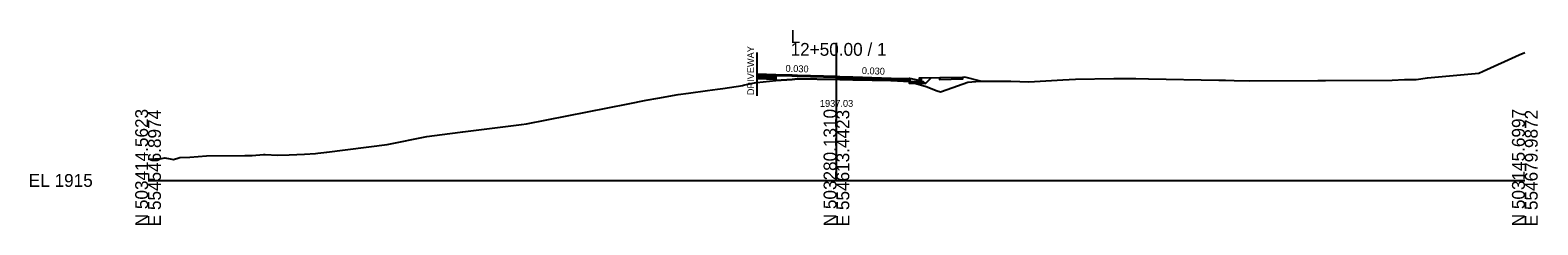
# Model space of a CAD drawing. Extents: x -26 to 4603, y -10 to 4703.
# Drawn here: x -25.7 to 302.8, y 1060.3 to 1102.8 of the extents above; entities that cross this region are included whole.
import ezdxf

# ---------------------------------------------------------------- set-up
doc = ezdxf.new("R2010")
doc.units = 0
for name, color, linetype in [('Default', 7, 'Continuous'), ('Exist Cross Section Cell', 7, 'Continuous'), ('Exist XS Ground Line', 7, 'Continuous'), ('Prop CMT Pvmt Course 1', 7, 'Continuous'), ('Prop CMT Pvmt Course 2', 7, 'Continuous'), ('Prop CMT Pvmt Course 3', 7, 'Continuous'), ('Prop CMT Pvmt Milling', 7, 'Continuous'), ('Prop CMT Shear Line', 7, 'Continuous'), ('Prop CMT Shld Paved Course 2', 7, 'Continuous'), ('Prop CMT Subgrade Earthwork', 7, 'Continuous'), ('Prop Conc 4in Sidewalk', 7, 'Continuous'), ('Prop Conc Curb and Gutter', 7, 'Continuous'), ('Prop Corridor Mesh Bottom', 7, 'Continuous'), ('Prop XS Finish Grade', 7, 'Continuous'), ('Prop XS Label Text', 7, 'Continuous'), ('Prop XS Shear Point Element', 7, 'Continuous'), ('Prop XS Shear Point Label', 7, 'Continuous'), ('Prop XS SS Elevation Text', 7, 'Continuous')]:
    doc.layers.add(name, color=color, linetype=linetype)

msp = doc.modelspace()

# ---------------------------------------------------------------- linework, layer by layer
at = {"layer": 'Exist Cross Section Cell'}
for p, q in [((150, 1070), (150, 1100)), ((0, 1070), (150, 1070)), ((150, 1070), (300, 1070))]:
    msp.add_line(p, q, dxfattribs=at)
at = {"layer": 'Exist XS Ground Line'}
msp.add_lwpolyline([(0, 1074.67), (2.92, 1074.82), (3.65, 1074.97), (4.8, 1074.71), (5.52, 1074.59), (6.72, 1074.96), (6.94, 1075.02), (9.11, 1075.1), (12.76, 1075.38), (21.08, 1075.41), (21.67, 1075.44), (22.66, 1075.48), (25.13, 1075.65), (25.52, 1075.66), (28.17, 1075.51), (30.73, 1075.57), (34.08, 1075.7), (36.49, 1075.89), (36.99, 1075.92), (38.94, 1076.19), (52.08, 1077.83), (60.71, 1079.57), (65.78, 1080.25), (68.59, 1080.64), (80.8, 1082.11), (81.34, 1082.2), (82.46, 1082.38), (104.64, 1086.71), (108.52, 1087.54), (111.05, 1087.94), (115.49, 1088.78), (117.73, 1089.06), (121.9, 1089.6), (124.11, 1089.89), (125.21, 1090.05), (129.58, 1090.74), (129.63, 1090.75), (129.68, 1090.75), (129.7, 1090.76), (132.52, 1091.35), (132.63, 1091.36), (136.83, 1091.78), (140.36, 1092.05), (141.55, 1092.14), (150.73, 1092.02), (151.98, 1092.01), (153.55, 1091.97), (161.96, 1091.78), (164.61, 1091.64), (165.83, 1091.6), (166.3, 1091.43), (169.53, 1090.5), (171.98, 1089.55), (172.66, 1089.33), (174.12, 1089.84), (178.61, 1091.42), (181.24, 1091.64), (182.19, 1091.68), (187.5, 1091.69), (187.78, 1091.69), (187.98, 1091.68), (191.94, 1091.54), (199.32, 1091.94), (202.08, 1092.13), (210.41, 1092.21), (215.21, 1092.26), (218.03, 1092.16), (233.35, 1091.91), (234.78, 1091.85), (236.64, 1091.83), (240.06, 1091.76), (254.9, 1091.82), (255.94, 1091.8), (256.54, 1091.8), (271.12, 1091.87), (273.75, 1092.05), (276.35, 1092.04), (278.82, 1092.4), (289.98, 1093.42), (290.89, 1093.88), (298.74, 1097.4), (300, 1097.92)], dxfattribs=at)
at = {"layer": 'Prop CMT Pvmt Course 1'}
for points in [[(136.83, 1093.07), (132.74, 1093.2), (132.74, 1092.95), (132.74, 1092.95), (136.83, 1092.82), (136.83, 1092.82), (136.83, 1092.82), (136.83, 1093.07), (136.83, 1093.07)], [(141.55, 1092.93), (141.55, 1092.93), (140.36, 1092.97), (140.36, 1092.97), (136.83, 1093.07), (136.83, 1091.78), (136.83, 1091.78), (140.36, 1092.05), (140.36, 1092.05), (141.55, 1092.14), (141.55, 1092.14), (141.55, 1092.14), (150, 1092.03), (150, 1092.03), (150, 1092.68), (141.55, 1092.93), (141.55, 1092.93)], [(165.83, 1092.21), (165.83, 1091.6), (165.83, 1091.6), (164.61, 1091.64), (164.61, 1091.64), (161.96, 1091.78), (161.96, 1091.78), (153.55, 1091.97), (153.55, 1091.97), (151.98, 1092.01), (151.98, 1092.01), (151.98, 1092.01), (150.73, 1092.02), (150.73, 1092.02), (150, 1092.03), (150, 1092.03), (150, 1092.68), (150.73, 1092.66), (150.73, 1092.66), (151.98, 1092.62), (151.98, 1092.62), (151.98, 1092.62), (153.55, 1092.58), (153.55, 1092.58), (161.96, 1092.33), (161.96, 1092.33), (164.61, 1092.25), (164.61, 1092.25), (165.83, 1092.21)], [(165.83, 1092.21), (165.83, 1092.21), (165.83, 1091.96), (165.83, 1091.96), (165.83, 1091.96), (166, 1091.96), (166, 1091.96), (166, 1092.21), (165.83, 1092.21)]]:
    msp.add_lwpolyline(points, dxfattribs=at)
at = {"layer": 'Prop CMT Pvmt Course 2'}
for points in [[(136.83, 1092.82), (132.74, 1092.95), (132.74, 1092.61), (132.74, 1092.61), (136.83, 1092.49), (136.83, 1092.49), (136.83, 1092.49), (136.83, 1092.82), (136.83, 1092.82)], [(165.83, 1091.96), (165.83, 1091.96), (165.83, 1091.63), (165.83, 1091.63), (165.83, 1091.63), (166, 1091.62), (166, 1091.62), (166, 1091.96), (165.83, 1091.96)]]:
    msp.add_lwpolyline(points, dxfattribs=at)
at = {"layer": 'Prop CMT Pvmt Course 3'}
for points in [[(136.83, 1092.49), (132.74, 1092.61), (132.74, 1092.24), (132.74, 1092.24), (136.83, 1092.12), (136.83, 1092.12), (136.83, 1092.12), (136.83, 1092.49), (136.83, 1092.49)], [(165.83, 1091.63), (165.83, 1091.63), (165.83, 1091.25), (165.83, 1091.25), (165.83, 1091.25), (166, 1091.25), (166, 1091.25), (166, 1091.62), (165.83, 1091.63)], [(169, 1091.53), (166, 1091.62), (166, 1091.25), (166, 1091.25), (169.39, 1091.15), (169.39, 1091.15), (169.39, 1091.15), (169, 1091.53), (169, 1091.53)]]:
    msp.add_lwpolyline(points, dxfattribs=at)
at = {"layer": 'Prop CMT Pvmt Milling'}
for points in [[(150, 1092.03), (141.55, 1092.14), (141.55, 1092.14), (141.55, 1092.14), (140.36, 1092.05), (140.36, 1092.05), (136.83, 1091.78)], [(165.83, 1091.6), (164.61, 1091.64), (164.61, 1091.64), (161.96, 1091.78), (161.96, 1091.78), (153.55, 1091.97), (153.55, 1091.97), (151.98, 1092.01), (151.98, 1092.01), (151.98, 1092.01), (150.73, 1092.02), (150.73, 1092.02), (150, 1092.03)]]:
    msp.add_lwpolyline(points, dxfattribs=at)
at = {"layer": 'Prop CMT Shld Paved Course 2'}
for points in [[(141.55, 1092.68), (141.55, 1092.68), (140.36, 1092.72), (140.36, 1092.72), (136.83, 1092.82), (136.83, 1091.78), (136.83, 1091.78), (140.36, 1092.05), (140.36, 1092.05), (141.55, 1092.14), (141.55, 1092.14), (141.55, 1092.14), (150, 1092.03), (150, 1092.03), (150, 1092.43), (141.55, 1092.68), (141.55, 1092.68)], [(165.83, 1091.96), (165.83, 1091.6), (165.83, 1091.6), (164.61, 1091.64), (164.61, 1091.64), (163.68, 1091.69), (163.68, 1091.69), (161.96, 1091.74), (161.96, 1091.74), (161.96, 1091.74), (156.61, 1091.9), (153.55, 1091.97), (153.55, 1091.97), (151.98, 1092.01), (151.98, 1092.01), (151.98, 1092.01), (150.73, 1092.02), (150.73, 1092.02), (150, 1092.03), (150, 1092.03), (150, 1092.43), (150.73, 1092.41), (150.73, 1092.41), (151.98, 1092.37), (151.98, 1092.37), (151.98, 1092.37), (153.55, 1092.33), (153.55, 1092.33), (161.96, 1092.08), (161.96, 1092.08), (164.61, 1092), (164.61, 1092), (165.83, 1091.96)]]:
    msp.add_lwpolyline(points, dxfattribs=at)
at = {"layer": 'Prop CMT Subgrade Earthwork'}
for points in [[(132.74, 1092.24), (136.83, 1092.12), (136.83, 1092.12)], [(169.39, 1091.15), (165.83, 1091.25), (165.83, 1091.25)], [(170.59, 1092.35), (169.39, 1091.15), (169.39, 1091.15)]]:
    msp.add_lwpolyline(points, dxfattribs=at)
at = {"layer": 'Prop Conc 4in Sidewalk'}
msp.add_lwpolyline([(172.5, 1092.39), (172.5, 1092.39), (172.49, 1092.05), (172.49, 1092.05), (172.49, 1092.05), (177.51, 1092.15), (177.51, 1092.15), (177.5, 1092.49), (172.5, 1092.39)], dxfattribs=at)
at = {"layer": 'Prop Conc Curb and Gutter'}
msp.add_lwpolyline([(168, 1091.81), (166, 1092.21), (166, 1091.62), (166, 1091.62), (168.5, 1091.55), (168.5, 1091.55), (168.5, 1091.55), (168.5, 1092.31), (168.5, 1092.31), (168, 1092.31), (168, 1091.81), (168, 1091.81), (168, 1091.81)], dxfattribs=at)
at = {"layer": 'Prop Corridor Mesh Bottom'}
msp.add_lwpolyline([(166, 1092.21), (166, 1091.96)], dxfattribs=at)
at = {"layer": 'Prop XS Finish Grade'}
for points in [[(172.5, 1092.39), (168.5, 1092.31), (168.5, 1092.31)], [(178, 1092.5), (177.5, 1092.49), (177.5, 1092.49)], [(181.39, 1091.65), (181.39, 1091.65), (178, 1092.5)]]:
    msp.add_lwpolyline(points, dxfattribs=at)
at = {"layer": 'Prop XS Shear Point Element'}
msp.add_line((132.74, 1088.43), (132.74, 1097.92), dxfattribs=at)

# ---------------------------------------------------------------- texts
at = {"layer": 'Default'}
msp.add_text('-', height=0.0001, dxfattribs=at).set_placement((0, 1070))
at = {"layer": 'Exist Cross Section Cell'}
for s, p in [('L', (140, 1100)), ('12+50.00 / 1', (140, 1097.2)), ('EL 1915', (-26, 1068.6))]:
    msp.add_text(s, height=2.8, dxfattribs=at).set_placement(p)
for s, p in [('N 503414.5623', (0, 1060)), ('E 554546.8974', (2.8, 1060)), ('N 503280.1310', (150, 1060)), ('E 554613.4423', (152.8, 1060)), ('N 503145.6997', (300, 1060)), ('E 554679.9872', (302.8, 1060))]:
    msp.add_text(s, height=2.8, rotation=90, dxfattribs=at).set_placement(p)
at = {"layer": 'Prop CMT Shear Line'}
for p in [(132.74, 1093.19), (150, 1092.68), (166, 1092.21), (166, 1092.21), (168, 1091.81), (172.5, 1092.39), (177.5, 1092.49), (178, 1092.5), (181.39, 1091.65)]:
    msp.add_text('X', height=0.0025, dxfattribs=at).set_placement(p)
at = {"layer": 'Prop XS Label Text'}
for rotation, p in [(358.299, (138.89, 1093.71)), (358.298, (155.52, 1093.22))]:
    msp.add_text('0.030', height=1.5, rotation=rotation, dxfattribs=at).set_placement(p)
at = {"layer": 'Prop XS Shear Point Label'}
msp.add_text('DRIVEWAY', height=1.5, rotation=90, dxfattribs=at).set_placement((132.07, 1088.61))
at = {"layer": 'Prop XS SS Elevation Text'}
msp.add_text('1937.03', height=1.5, dxfattribs=at).set_placement((146.4, 1086.06))

doc.saveas('drawing.dxf')
